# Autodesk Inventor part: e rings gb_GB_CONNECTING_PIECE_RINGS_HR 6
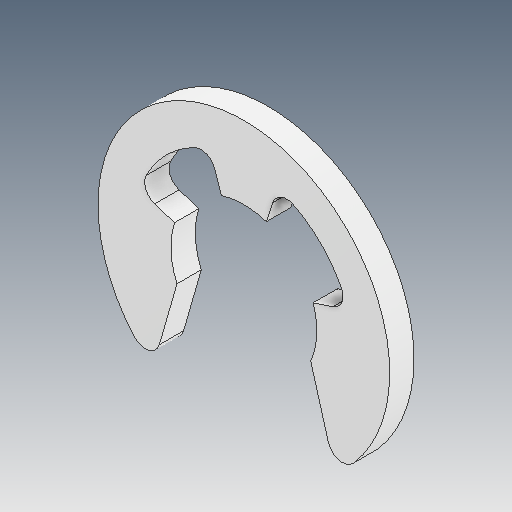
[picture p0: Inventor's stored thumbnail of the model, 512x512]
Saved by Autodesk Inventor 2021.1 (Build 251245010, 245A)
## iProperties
Created: 2021-05
Part Number: e rings gb_GB_CONNECTING_PIECE_RINGS_HR 6
Material: Ogólny
Document SubType Name: Modeling
Designer: user
Density: 1 g/cm^3
Appearance: Domyślna
Author: user
Revision Number: ÈÎºÎ
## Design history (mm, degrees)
feature "ÊäÈë1"
node "Bryła1"
